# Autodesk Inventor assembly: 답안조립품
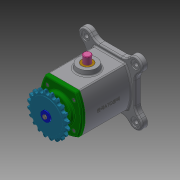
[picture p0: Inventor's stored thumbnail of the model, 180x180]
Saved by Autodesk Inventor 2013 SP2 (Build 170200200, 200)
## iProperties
Created: 2022-01
Part Number: 답안조립품
Document SubType Name: Assembly
Designer: a
Author: a
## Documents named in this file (13)
- C:\Users\a\Desktop\720106V1004\답안조립품.iam
- C:\Users\a\Desktop\720106V1004\본체.ipt
- C:\Users\a\Desktop\720106V1004\베어링 6203.ipt
- C:\Users\a\Desktop\720106V1004\볼트 M4 x 12.ipt
- C:\Users\a\Desktop\720106V1004\부시.ipt
- C:\Users\a\Desktop\720106V1004\스프로킷.ipt
- C:\Users\a\Desktop\720106V1004\슬라이더.ipt
- C:\Users\a\Desktop\720106V1004\오일 실 17 x 30 x 8.ipt
- C:\Users\a\Desktop\720106V1004\와셔 4 x 20.ipt
- C:\Users\a\Desktop\720106V1004\육각머리볼트 M4.ipt
- C:\Users\a\Desktop\720106V1004\커버.ipt
- C:\Users\a\Desktop\720106V1004\키 5 x 5.ipt
- C:\Users\a\Desktop\720106V1004\편심축.ipt
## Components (8 placed, 1 different names)
1. M4x0.7x12:1
2. M4x0.7x12:3
3. M4x0.7x12:4
4. M4x0.7x12:5
5. M4x0.7x12:2
6. M4x0.7x12:6
7. M4x0.7x12:7
8. M4x0.7x12:8
